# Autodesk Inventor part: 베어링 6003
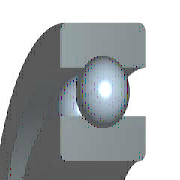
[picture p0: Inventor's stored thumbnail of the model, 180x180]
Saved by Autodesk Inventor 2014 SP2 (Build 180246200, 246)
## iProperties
IsCustomPart: 1
Company: 한국ATC센터
Created: 2014-07
Part Number: 베어링 6003
Material: 강, 연강
Description: 깊은 그루브 볼 베어링
Document SubType Name: Modeling
Standard: KS B 2023
Designer: KYOUNG IL JANG
Standards Organization: KS
Language: ko-KR
Size Designation: 6003 - 17 x 35 x 10
Categories: <MemberInstance><Categories><Category DisplayName="샤프트 부품" InternalName="7f7aeb1f-a693-4053-b835-cee3144e0d98" Mnemonic="SHFT"><Category DisplayName="베어링" Inter
Density: 1 g/cm^3
Appearance: 강철
Author: KYOUNG IL JANG
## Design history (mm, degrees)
sketch "스케치" dims "d0" = 4.68 (= -0.26 x WD + 0.26 x BD)
  geometry: L1 (2.66, 13)-(7.34, 13); L2 (5, 13)-(5, 10.66); L3 (5, 13)-(5, 15.34); L4 (3.261, 11.434)-(0, 11.434); L5 (0, 8.5)-(10, 8.5); L6 (3.261, 14.566)-(0, 14.566); L7 (0, 17.5)-(10, 17.5); L8 (10, 8.5)-(10, 11.434); L9 (6.739, 11.434)-(10, 11.434); L10 (6.739, 14.566)-(10, 14.566); L11 (10, 17.5)-(10, 14.566); L12 (-1.4, 0)-(8.4, 0) reference; L13 (0, -0.3)-(0, 5.3) reference
  constraints: 22 end point, 4 point on line, 2 collinear, 2 perpendicular, 2 symmetric about line, 1 midpoint, 1 parallel, 14 other
  dimensions: "d9" = 17 diameter of L5 L12 (= WD); "d11" = 35 diameter of L7 L12 (= BD); "d12" = 10 distance between parallel lines of L8 L13 (= KB); "d13" = 22.868 diameter of L9 L12 (= 0.326 x BD + 0.674 x WD)
revolve "본체" stored, may be unused: angle "d6" = 90 deg
revolve "볼" stored, may be unused: angle "d7" = 90 deg
pattern_circular "IDS_ARRAYBALL[SIMPL:T]" dims angle "d3" = 360 deg
body "Solid1"
fillet "모깎기1" dims "d1" = 0.3 (= KRS)
other parameters: "WD" = 17 [user parameter; used in 5 equation terms], "BD" = 35 [user parameter; used in 5 equation terms], "KB" = 10 [user parameter; used in 1 equation term], "KRS" = 0.3 [user parameter; used in 1 equation term], "d4" = 0, "d5" = 0, "d8" = 0, "d14" = 0, "d15" = 0, "BBA" = 0 [user parameter], "BC0" = 3250000 [user parameter], "BC" = 6050000 [user parameter], "BR" = 17.5 (= 0.5 x BD) [user parameter], "WR" = 8.5 (= 0.5 x WD) [user parameter]
